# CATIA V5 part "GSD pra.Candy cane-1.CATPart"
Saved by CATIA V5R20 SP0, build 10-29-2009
Part number: GSD pra.Candy cane-1
Bounding box of the stored display mesh (mm): x -5.072 to 5.077, y -5.08 to 116.836, z 0 to 314.85
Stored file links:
  C:\Users\PSJ\Desktop\카티아\GSD연습\GSD pra.Candy cane-1.CATPart
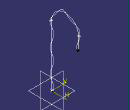
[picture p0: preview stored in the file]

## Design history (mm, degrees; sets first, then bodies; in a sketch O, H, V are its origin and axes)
Body1 (main body)
  Point1: (0, 0, 0)
  Line1: type PtDir, RefPoint Point1, Direction xy-plane, Start 0, End 254
  CurvePar1: Offset Line1, Offset2 0, Offset1 111.76, Support yz-plane
  Circle1: type BitangentPt, Start 0, End 180, Element1 Line1, Element2 CurvePar1, RefPoint vertex of Line1
  Line2: type PtDir, RefPoint vertex of CurvePar1, Direction CurvePar1, Start 0, End 53.0478
  Join1: Elements (Line1; Circle1; Line2)
  CurveSmooth1: CurveToSmooth Join1
  Sweep1: type Circle, Guide CurveSmooth1, Radius 5.08
  Line3: type PtDir, RefPoint Point1, Direction (0, 1, 0), Start 0, End 25.4
  Sweep2: type Unspec, Profile Line3, Guide CurveSmooth1, Reference yz-plane, RefAngle 0, RefAngle2 1800
  Intersect1: ToIntersect1 Sweep2, ToIntersect2 Sweep1
  Sketch1 on xy-plane, origin (0, 0, 0), H (0, 1, 0), V (-1, 0, 0)
    arc A1 centre (0, 0) radius 5.08 from (5.0279, 0.7257) to (0.7257, 5.0279) ccw
    line L1 (0, 0) -> (0, 4.3994)
    line L2 (0, 0) -> (4.3994, 0)
    arc A2 centre (4.3994, 0.635) radius 0.635 from (5.0279, 0.7257) to (4.3994, 0) cw
    arc A3 centre (0.635, 4.3994) radius 0.635 from (0.7257, 5.0279) to (0, 4.3994) ccw
    radius A2 = 0.635
    radius A3 = 0.635
    radius A1 = 5.08
    vertical: L1 V
    horizontal: L2 H
    tangency: A2 L2, A2 A1, A3 L1, A3 A1
  CurveSmooth2: CurveToSmooth Intersect1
